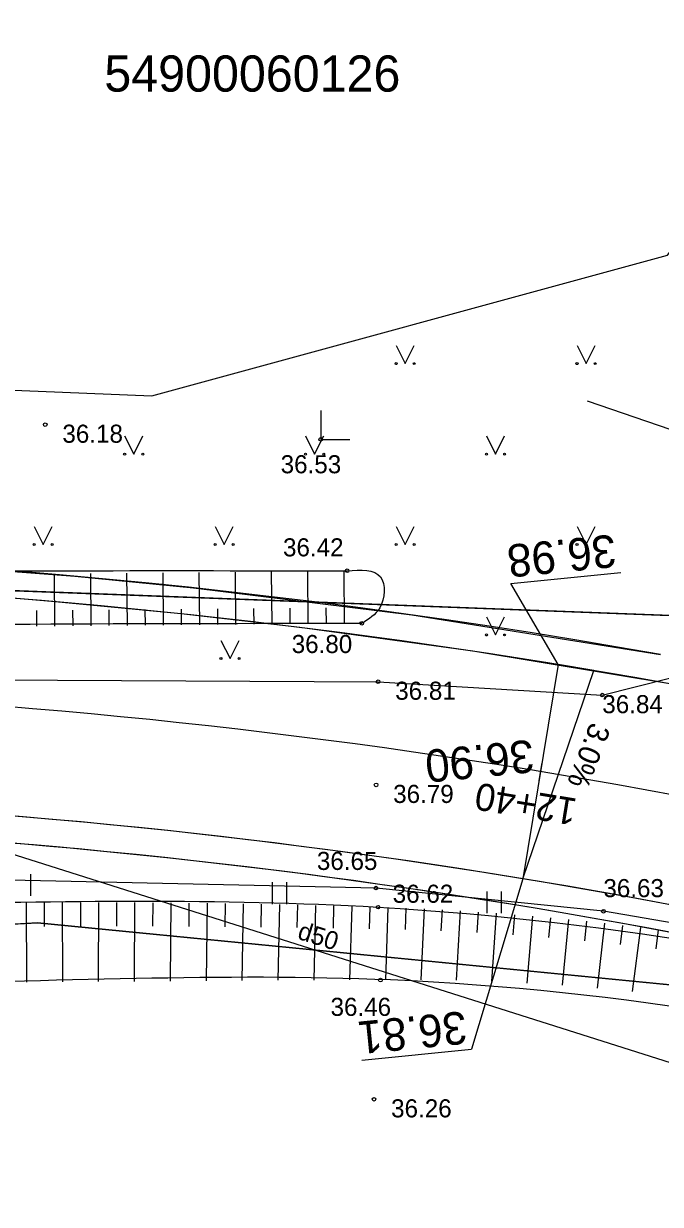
# Model space of a CAD drawing. Extents: x 469981 to 472086, y 246785 to 247785.
# Drawn here: x 470851.96 to 470869.55, y 247209.26 to 247241.9 of the extents above; entities that cross this region are included whole.
import ezdxf

# ---------------------------------------------------------------- set-up
doc = ezdxf.new("R2010")
doc.units = 0
for name, color, linetype in [('0_922', 7, 'Continuous'), ('0_Asfalta_mala', 7, 'Continuous'), ('0_Asfalta_Nomale', 7, 'Continuous'), ('0_Ruut_Braukt', 7, 'Continuous'), ('0_Ruut_nomale', 7, 'Continuous'), ('0_vertikals', 7, 'Continuous'), ('0_vertkals_cipari', 7, 'Continuous'), ('21', 7, 'Continuous'), ('6_piketaza', 7, 'Continuous'), ('CELI_CMAL_####_####_#', 7, 'Continuous'), ('DREN_VADP_####_####_#', 7, 'Continuous'), ('DREN_VADP_####_TKST_#', 7, 'Continuous'), ('DREN_VADP_KLKT_####_#', 7, 'Continuous'), ('RAMI_UZMR_####_####_#', 7, 'Continuous'), ('RELJ_AATZ_####_TKST_#', 7, 'Continuous'), ('RELJ_ELEM_####_####_#', 7, 'Continuous'), ('RELJ_NOGA_####_####_#', 7, 'Continuous'), ('RELJ_NOGL_####_####_#', 7, 'Continuous'), ('ROBZ_PROJ_####_####_#', 7, 'Continuous'), ('ROBZ_PROJ_####_TKST_#', 7, 'Continuous'), ('ROBZ_UZMR_####_####_#', 7, 'Continuous'), ('TERT_ELEM_####_####_#', 7, 'Continuous')]:
    doc.layers.add(name, color=color, linetype=linetype)

msp = doc.modelspace()

# ---------------------------------------------------------------- linework, layer by layer
at = {"layer": '0_922'}
msp.add_arc((470837.1, 247043.596), 180, 70.3373, 103.67202, dxfattribs=at)
at = {"layer": '0_Asfalta_mala'}
for radius in [183, 177]:
    msp.add_arc((470837.1, 247043.596), radius, 70.3373, 103.67202, dxfattribs=at)
at = {"layer": '0_Asfalta_Nomale'}
for radius, start in [(183.75, 79.82731), (176.25, 70.3373)]:
    msp.add_arc((470837.1, 247043.596), radius, start, 103.67202, dxfattribs=at)
at = {"layer": '0_Ruut_Braukt'}
for radius in [183, 177]:
    msp.add_arc((470837.1, 247043.596), radius, 70.3373, 103.67202, dxfattribs=at)
at = {"layer": '0_Ruut_nomale'}
for points in [[(470829.387, 247227.185), (470834.194, 247227.323), (470838.036, 247227.344), (470840.901, 247227.307), (470848.504, 247226.992), (470853.37, 247226.625), (470856.655, 247226.303), (470862.687, 247225.556), (470869.555, 247224.458)], [(470869.98, 247223.618), (470864.374, 247224.552), (470859.593, 247225.209), (470856.316, 247225.585), (470852.732, 247225.927), (470851.104, 247226.06), (470844.162, 247226.46), (470840.457, 247226.566), (470838.246, 247226.593), (470834.465, 247226.577), (470829.479, 247226.438)]]:
    msp.add_lwpolyline(points, dxfattribs=at)
for radius, start in [(177, 72.7764), (176.25, 72.74503)]:
    msp.add_arc((470837.1, 247043.596), radius, start, 103.67202, dxfattribs=at)
at = {"layer": '0_vertikals'}
for p, q in [((470865.425, 247226.424), (470868.457, 247226.728)), ((470866.728, 247224.182), (470865.425, 247226.424)), ((470865.757, 247218.261), (470864.333, 247213.551)), ((470861.301, 247213.246), (470864.333, 247213.551))]:
    msp.add_line(p, q, dxfattribs=at)
msp.add_lwpolyline([(470865.757, 247218.261), (470867.715, 247224.018), (470866.728, 247224.182)], close=True, dxfattribs=at)
at = {"layer": '21'}
msp.add_arc((470837.1, 247043.596), 180, 70.3373, 103.67202, dxfattribs=at)
at = {"layer": '6_piketaza'}
msp.add_lwpolyline([(470866.202, 247220.975), (470866.283, 247221.468)], dxfattribs=at)
at = {"layer": 'CELI_CMAL_####_####_#'}
for points in [[(470678.613, 247193.526), (470707.455, 247200.791), (470732.512, 247206.741), (470762.073, 247213.437), (470788.208, 247218.626), (470817.367, 247222.191), (470831.408, 247222.915), (470849.341, 247223.769), (470861.754, 247223.708), (470867.949, 247223.336), (470870.754, 247224.045), (470872.402, 247225.837), (470874.431, 247230.012), (470874.14, 247233.92), (470872.817, 247237.597), (470871.759, 247240.057)], [(470881.196, 247215.092), (470867.979, 247217.363), (470861.696, 247218.004), (470848.617, 247218.285), (470830.624, 247217.903), (470817.243, 247216.917), (470789.541, 247213.218), (470761.584, 247207.361), (470733.919, 247200.757), (470708.074, 247194.55), (470680.531, 247188.015)]]:
    msp.add_lwpolyline(points, dxfattribs=at)
at = {"layer": 'DREN_VADP_####_####_#'}
msp.add_lwpolyline([(470845.346, 247220.939), (470990.896, 247174.789)], dxfattribs=at)
at = {"layer": 'DREN_VADP_KLKT_####_#'}
msp.add_lwpolyline([(470998.012, 247199.651), (470980.588, 247192.708), (470867.536, 247231.459)], dxfattribs=at)
at = {"layer": 'RAMI_UZMR_####_####_#'}
msp.add_lwpolyline([(470560.64, 247175.144), (470793.366, 247232.231), (470822.25, 247233), (470855.497, 247231.608), (470869.75, 247235.5), (470872.288, 247238.827), (470875.523, 247240.24), (470882.387, 247236.327), (470885.36, 247235.904), (470900.348, 247222.872), (470947.872, 247208.875), (470978.25, 247197.629), (470994.287, 247200.731), (471010.572, 247199.465), (471044.448, 247201.846)], dxfattribs=at)
at = {"layer": 'RELJ_ELEM_####_####_#'}
for centre in [(470852.555, 247230.813), (470860.17, 247230.406), (470860.897, 247226.774), (470861.302, 247225.322), (470861.754, 247223.708), (470867.949, 247223.337), (470861.697, 247220.856), (470861.696, 247218.004), (470861.752, 247217.476), (470867.979, 247217.363), (470861.817, 247215.459), (470861.64, 247212.165)]:
    msp.add_circle(centre, 0.05, dxfattribs=at)
at = {"layer": 'RELJ_NOGA_####_####_#'}
for p, q in [((470853.825, 247225.255), (470853.812, 247226.696)), ((470854.825, 247225.264), (470854.812, 247226.707)), ((470855.825, 247225.273), (470855.812, 247226.718)), ((470856.825, 247225.282), (470856.812, 247226.729)), ((470857.825, 247225.291), (470857.812, 247226.74)), ((470858.825, 247225.3), (470858.812, 247226.751)), ((470859.825, 247225.309), (470859.812, 247226.762)), ((470860.825, 247225.318), (470860.812, 247226.773)), ((470852.825, 247225.246), (470852.812, 247226.685)), ((470856.325, 247225.277), (470856.321, 247225.711)), ((470857.325, 247225.286), (470857.321, 247225.721)), ((470858.325, 247225.295), (470858.321, 247225.73)), ((470859.325, 247225.304), (470859.321, 247225.74)), ((470860.325, 247225.313), (470860.321, 247225.749)), ((470852.325, 247225.241), (470852.321, 247225.672)), ((470853.325, 247225.25), (470853.321, 247225.682)), ((470854.325, 247225.259), (470854.321, 247225.692)), ((470855.325, 247225.268), (470855.321, 247225.701)), ((470852.026, 247217.603), (470852.035, 247215.402)), ((470852.026, 247217.603), (470852.035, 247215.402)), ((470852.526, 247217.605), (470852.528, 247216.945)), ((470852.526, 247217.605), (470852.528, 247216.945)), ((470853.026, 247217.606), (470853.03, 247215.41)), ((470853.026, 247217.606), (470853.03, 247215.41)), ((470853.526, 247217.606), (470853.526, 247216.948)), ((470853.526, 247217.606), (470853.526, 247216.948)), ((470854.026, 247217.605), (470854.022, 247215.418)), ((470854.026, 247217.605), (470854.022, 247215.418)), ((470854.526, 247217.604), (470854.524, 247216.949)), ((470854.526, 247217.604), (470854.524, 247216.949)), ((470855.026, 247217.601), (470855.015, 247215.425)), ((470855.026, 247217.601), (470855.015, 247215.425)), ((470855.526, 247217.598), (470855.521, 247216.947)), ((470855.526, 247217.598), (470855.521, 247216.947)), ((470856.026, 247217.593), (470856.005, 247215.432)), ((470856.026, 247217.593), (470856.005, 247215.432)), ((470856.526, 247217.588), (470856.519, 247216.942)), ((470856.526, 247217.588), (470856.519, 247216.942)), ((470857.026, 247217.582), (470856.999, 247215.439)), ((470857.026, 247217.582), (470856.999, 247215.439)), ((470857.526, 247217.575), (470857.517, 247216.935)), ((470857.526, 247217.575), (470857.517, 247216.935)), ((470858.026, 247217.567), (470857.99, 247215.446)), ((470858.026, 247217.567), (470857.99, 247215.446)), ((470858.526, 247217.558), (470858.514, 247216.925)), ((470858.526, 247217.558), (470858.514, 247216.925)), ((470859.026, 247217.548), (470858.983, 247215.453)), ((470859.026, 247217.548), (470858.983, 247215.453)), ((470859.526, 247217.537), (470859.511, 247216.913)), ((470859.526, 247217.537), (470859.511, 247216.913)), ((470860.026, 247217.525), (470859.973, 247215.459)), ((470860.026, 247217.525), (470859.973, 247215.459)), ((470860.525, 247217.512), (470860.509, 247216.897)), ((470860.525, 247217.512), (470860.509, 247216.897)), ((470861.025, 247217.498), (470860.967, 247215.465)), ((470861.025, 247217.498), (470860.967, 247215.465)), ((470861.525, 247217.483), (470861.506, 247216.879)), ((470861.525, 247217.483), (470861.506, 247216.879)), ((470862.025, 247217.467), (470861.958, 247215.471)), ((470862.025, 247217.467), (470861.958, 247215.471)), ((470862.524, 247217.448), (470862.5, 247216.855)), ((470862.524, 247217.448), (470862.5, 247216.855)), ((470863.024, 247217.426), (470862.93, 247215.471)), ((470863.024, 247217.426), (470862.93, 247215.471)), ((470863.523, 247217.4), (470863.491, 247216.82)), ((470863.523, 247217.4), (470863.491, 247216.82)), ((470864.022, 247217.372), (470863.91, 247215.456)), ((470864.022, 247217.372), (470863.91, 247215.456)), ((470864.522, 247217.341), (470864.484, 247216.771)), ((470864.522, 247217.341), (470864.484, 247216.771)), ((470865.02, 247217.306), (470864.884, 247215.425)), ((470865.02, 247217.306), (470864.884, 247215.425)), ((470865.519, 247217.268), (470865.475, 247216.709)), ((470865.519, 247217.268), (470865.475, 247216.709)), ((470866.017, 247217.227), (470865.86, 247215.379)), ((470866.017, 247217.227), (470865.86, 247215.379)), ((470866.515, 247217.183), (470866.465, 247216.633)), ((470866.515, 247217.183), (470866.465, 247216.633)), ((470867.013, 247217.136), (470866.836, 247215.317)), ((470867.013, 247217.136), (470866.836, 247215.317)), ((470867.51, 247217.085), (470867.453, 247216.543)), ((470867.51, 247217.085), (470867.453, 247216.543)), ((470868.007, 247217.031), (470867.806, 247215.239)), ((470868.007, 247217.031), (470867.806, 247215.239)), ((470868.504, 247216.973), (470868.441, 247216.439)), ((470868.504, 247216.973), (470868.441, 247216.439)), ((470869, 247216.913), (470868.777, 247215.145)), ((470869, 247216.913), (470868.777, 247215.145)), ((470869.496, 247216.848), (470869.426, 247216.321)), ((470869.496, 247216.848), (470869.426, 247216.321))]:
    msp.add_line(p, q, dxfattribs=at)
for points in [[(470606.183, 247176.676), (470630.141, 247182.622), (470654.6, 247188.654), (470677.992, 247194.648), (470707.339, 247201.373), (470732.104, 247207.628), (470762.069, 247214.507), (470787.98, 247219.522), (470817.319, 247223.525), (470842.975, 247225.157), (470861.302, 247225.322)], [(470443.762, 247118.331), (470443.88, 247120.814), (470444.471, 247122.233), (470445.96, 247123.747), (470447.74, 247124.344), (470466.701, 247130.323), (470490.205, 247137.037), (470509.522, 247142.633), (470536.42, 247149.583), (470558.637, 247154.955), (470585.403, 247162.504), (470607.875, 247168.231), (470633.412, 247175.414), (470656.062, 247180.759), (470680.788, 247187.471), (470708.074, 247193.923), (470734.191, 247200.317), (470761.697, 247206.456), (470789.773, 247212.754), (470817.257, 247216.179), (470830.019, 247217.144), (470848.586, 247217.569), (470861.752, 247217.476), (470881.066, 247214.264), (470905.336, 247205.96), (470932.738, 247196.11), (470958.906, 247187.141), (470978.102, 247181.086)]]:
    msp.add_spline(points, degree=3, dxfattribs=at)
at = {"layer": 'RELJ_NOGL_####_####_#'}
for points in [[(470606.139, 247178.172), (470629.32, 247183.824), (470654.592, 247190.289), (470677.819, 247195.89), (470706.841, 247202.594), (470731.579, 247208.797), (470762.066, 247216.088), (470787.493, 247220.75), (470816.99, 247225.543), (470831.338, 247226.448), (470860.897, 247226.774)], [(470860.897, 247226.774), (470861.822, 247226.603), (470861.798, 247225.751), (470861.302, 247225.322)], [(470444.636, 247118.184), (470444.802, 247120.028), (470444.991, 247120.926), (470445.558, 247121.73), (470446.408, 247122.251), (470448.872, 247122.621), (470466.486, 247128.526), (470490.665, 247135.792), (470509.603, 247140.94), (470537.55, 247147.945), (470558.966, 247153.542), (470586.086, 247160.934), (470607.922, 247166.842), (470634.241, 247173.648), (470681.28, 247185.658), (470708.292, 247192.117), (470734.878, 247198.699), (470761.457, 247204.922), (470790.498, 247211.068), (470817.148, 247213.701), (470830.618, 247215.209), (470848.022, 247215.369), (470862.099, 247215.472), (470880.883, 247212.412), (470904.425, 247203.826), (470932.21, 247193.701), (470958.298, 247186.024), (470977.689, 247180.167)]]:
    msp.add_spline(points, degree=3, dxfattribs=at)
at = {"layer": 'ROBZ_PROJ_####_####_#'}
for points in [[(470613.752, 247179.765), (470688.303, 247197.106), (470783.692, 247219.293), (470809.088, 247224.67), (470845.751, 247226.447), (470876.169, 247225.296), (470921.641, 247209.731), (470967.353, 247194.084), (470989.48, 247188.802), (471001.509, 247189.266), (471050.609, 247195.379), (471093.674, 247200.298), (471124.72, 247213.54), (471341.261, 247348.2), (471524.883, 247464.852)], [(471398.351, 247372.094), (471346.741, 247338.478), (471133.176, 247205.05), (471108.425, 247194.786), (471087.339, 247189.709), (471023.306, 247181.157), (470962.604, 247185.245), (470905.63, 247205.857), (470878.75, 247214.454), (470852.344, 247217.039), (470815.743, 247215.147), (470778.583, 247209.26), (470718.669, 247194.633), (470636.973, 247175.147), (470468.364, 247124.23), (470431.624, 247112.202), (470396.219, 247097.502), (470371.503, 247083.47), (470275.956, 246992.729), (470152.342, 246907.761), (470066.737, 246851.23)], [(470900.878, 247270.342), (470921.641, 247209.731), (470876.169, 247225.296), (470845.751, 247226.447), (470809.088, 247224.67), (470797.907, 247259.877)]]:
    msp.add_lwpolyline(points, dxfattribs=at)
at = {"layer": 'ROBZ_UZMR_####_####_#'}
msp.add_lwpolyline([(470722.834, 247152.788), (470718.669, 247194.633), (470778.583, 247209.26), (470815.743, 247215.147), (470852.344, 247217.039), (470878.75, 247214.454), (470905.63, 247205.857), (470962.604, 247185.245), (470963.67, 247151.03)], dxfattribs=at)
at = {"layer": 'TERT_ELEM_####_####_#'}
for p, q in [((470862.25, 247233), (470862.5, 247232.5)), ((470862.5, 247232.5), (470862.75, 247233)), ((470867.25, 247233), (470867.5, 247232.5)), ((470867.5, 247232.5), (470867.75, 247233)), ((470860.17, 247231.206), (470860.17, 247230.406)), ((470854.75, 247230.5), (470855, 247230)), ((470855, 247230), (470855.25, 247230.5)), ((470859.75, 247230.5), (470860, 247230)), ((470860, 247230), (470860.25, 247230.5)), ((470860.17, 247230.406), (470860.97, 247230.406)), ((470864.75, 247230.5), (470865, 247230)), ((470865, 247230), (470865.25, 247230.5)), ((470852.25, 247228), (470852.5, 247227.5)), ((470852.5, 247227.5), (470852.75, 247228)), ((470857.25, 247228), (470857.5, 247227.5)), ((470857.5, 247227.5), (470857.75, 247228)), ((470862.25, 247228), (470862.5, 247227.5)), ((470862.5, 247227.5), (470862.75, 247228)), ((470867.25, 247228), (470867.5, 247227.5)), ((470867.5, 247227.5), (470867.75, 247228)), ((470864.75, 247225.5), (470865, 247225)), ((470865, 247225), (470865.25, 247225.5)), ((470857.411, 247224.849), (470857.661, 247224.349)), ((470857.661, 247224.349), (470857.911, 247224.849)), ((470852.157, 247217.786), (470852.157, 247218.386)), ((470858.836, 247217.562), (470858.836, 247218.162)), ((470859.236, 247217.562), (470859.236, 247218.162)), ((470864.768, 247217.31), (470864.768, 247217.91)), ((470865.168, 247217.31), (470865.168, 247217.91))]:
    msp.add_line(p, q, dxfattribs=at)
for centre, radius in [((470862.25, 247232.5), 0.028), ((470862.75, 247232.5), 0.0263), ((470867.25, 247232.5), 0.028), ((470867.75, 247232.5), 0.0263), ((470854.75, 247230), 0.028), ((470855.25, 247230), 0.0263), ((470859.75, 247230), 0.028), ((470860.25, 247230), 0.0263), ((470864.75, 247230), 0.028), ((470865.25, 247230), 0.0263), ((470852.25, 247227.5), 0.028), ((470852.75, 247227.5), 0.0263), ((470857.25, 247227.5), 0.028), ((470857.75, 247227.5), 0.0263), ((470862.25, 247227.5), 0.028), ((470862.75, 247227.5), 0.0263), ((470867.25, 247227.5), 0.028), ((470867.75, 247227.5), 0.0263), ((470864.75, 247225), 0.028), ((470865.25, 247225), 0.0263), ((470857.411, 247224.349), 0.028), ((470857.911, 247224.349), 0.0263)]:
    msp.add_circle(centre, radius, dxfattribs=at)

# ---------------------------------------------------------------- texts
at = {"layer": '0_vertkals_cipari'}
for s, height, rotation, p in [('36.98', 0.9, 185.7316, (470868.28, 247227.782)), ('3.0%', 0.5993, 248.8233, (470867.629, 247222.616)), ('36.90', 0.9, 185.7316, (470866.014, 247222.11)), ('36.81', 0.9, 185.7316, (470864.156, 247214.605))]:
    msp.add_text(s, height=height, rotation=rotation, dxfattribs=at).set_placement(p)
at = {"layer": '6_piketaza'}
msp.add_text('12+40', height=0.75, rotation=170.6826, dxfattribs=at).set_placement((470867.285, 247220.468))
at = {"layer": 'DREN_VADP_####_TKST_#'}
msp.add_text('d50', height=0.5, rotation=342.4077, dxfattribs=at).set_placement((470859.498, 247216.609))
at = {"layer": 'RELJ_AATZ_####_TKST_#'}
for s, p in [('36.18', (470853.029, 247230.313)), ('36.53', (470859.061, 247229.469)), ('36.42', (470859.126, 247227.172)), ('36.80', (470859.366, 247224.5)), ('36.81', (470862.227, 247223.208)), ('36.84', (470867.949, 247222.837)), ('36.79', (470862.17, 247220.356)), ('36.65', (470860.062, 247218.504)), ('36.63', (470867.979, 247217.752)), ('36.62', (470862.157, 247217.597)), ('36.46', (470860.439, 247214.47)), ('36.26', (470862.113, 247211.665))]:
    msp.add_text(s, height=0.5, dxfattribs=at).set_placement(p)
at = {"layer": 'ROBZ_PROJ_####_TKST_#'}
msp.add_text('54900060126', height=1, dxfattribs=at).set_placement((470854.188, 247240.019))

doc.saveas('drawing.dxf')
